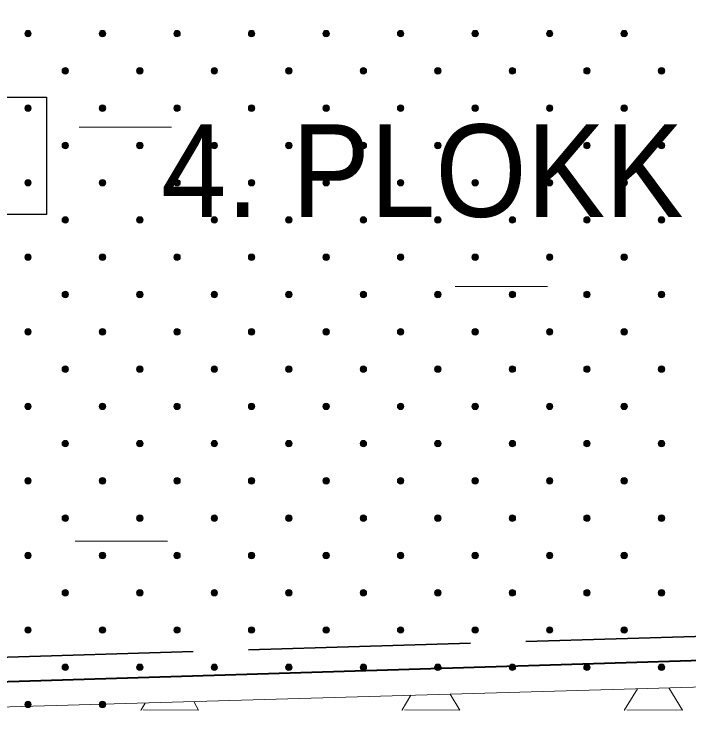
# Model space of a CAD drawing. Extents: x 640104 to 640970, y 6442278 to 6442689.
# Drawn here: x 640905.7 to 640927.6, y 6442508.94 to 6442531.71 of the extents above; entities that cross this region are included whole.
import ezdxf
from ezdxf.enums import TextEntityAlignment as Align

# ---------------------------------------------------------------- set-up
doc = ezdxf.new("R2010")
doc.units = 0
doc.header["$LTSCALE"] = 1.2
doc.linetypes.add('LONG_DASHED', pattern=[7.5, 6, -1.5])
for name, color, linetype, lineweight in [('31', 7, 'Continuous', 13), ('33', 7, 'Continuous', 13), ('35', 7, 'Continuous', 35), ('45', 7, 'Continuous', 13), ('46', 7, 'Continuous', 13), ('47', 7, 'Continuous', 13)]:
    doc.layers.add(name, color=color, linetype=linetype, lineweight=lineweight)

msp = doc.modelspace()

# ---------------------------------------------------------------- hatches: boundary and pattern name
at = {"layer": '45'}
for points in [[(640906.227, 6442531.149, 1), (640906.078, 6442531, 1)], [(640908.645, 6442531.149, 1), (640908.496, 6442531, 1)], [(640911.063, 6442531.149, 1), (640910.915, 6442531, 1)], [(640913.482, 6442531.149, 1), (640913.333, 6442531, 1)], [(640915.9, 6442531.149, 1), (640915.751, 6442531, 1)], [(640918.318, 6442531.149, 1), (640918.17, 6442531, 1)], [(640920.736, 6442531.149, 1), (640920.588, 6442531, 1)], [(640923.155, 6442531.149, 1), (640923.006, 6442531, 1)], [(640925.573, 6442531.149, 1), (640925.425, 6442531, 1)], [(640907.436, 6442529.94, 1), (640907.287, 6442529.791, 1)], [(640909.854, 6442529.94, 1), (640909.706, 6442529.791, 1)], [(640912.272, 6442529.94, 1), (640912.124, 6442529.791, 1)], [(640914.691, 6442529.94, 1), (640914.542, 6442529.791, 1)], [(640917.109, 6442529.94, 1), (640916.961, 6442529.791, 1)], [(640919.527, 6442529.94, 1), (640919.379, 6442529.791, 1)], [(640921.946, 6442529.94, 1), (640921.797, 6442529.791, 1)], [(640924.364, 6442529.94, 1), (640924.215, 6442529.791, 1)], [(640926.782, 6442529.94, 1), (640926.634, 6442529.791, 1)], [(640906.227, 6442528.731, 1), (640906.078, 6442528.582, 1)], [(640908.645, 6442528.731, 1), (640908.496, 6442528.582, 1)], [(640911.063, 6442528.731, 1), (640910.915, 6442528.582, 1)], [(640913.482, 6442528.731, 1), (640913.333, 6442528.582, 1)], [(640915.9, 6442528.731, 1), (640915.751, 6442528.582, 1)], [(640918.318, 6442528.731, 1), (640918.17, 6442528.582, 1)], [(640920.736, 6442528.731, 1), (640920.588, 6442528.582, 1)], [(640923.155, 6442528.731, 1), (640923.006, 6442528.582, 1)], [(640925.573, 6442528.731, 1), (640925.425, 6442528.582, 1)], [(640907.436, 6442527.522, 1), (640907.287, 6442527.373, 1)], [(640909.854, 6442527.522, 1), (640909.706, 6442527.373, 1)], [(640912.272, 6442527.522, 1), (640912.124, 6442527.373, 1)], [(640914.691, 6442527.522, 1), (640914.542, 6442527.373, 1)], [(640917.109, 6442527.522, 1), (640916.961, 6442527.373, 1)], [(640919.527, 6442527.522, 1), (640919.379, 6442527.373, 1)], [(640921.946, 6442527.522, 1), (640921.797, 6442527.373, 1)], [(640924.364, 6442527.522, 1), (640924.215, 6442527.373, 1)], [(640926.782, 6442527.522, 1), (640926.634, 6442527.373, 1)], [(640906.227, 6442526.312, 1), (640906.078, 6442526.164, 1)], [(640908.645, 6442526.312, 1), (640908.496, 6442526.164, 1)], [(640911.063, 6442526.312, 1), (640910.915, 6442526.164, 1)], [(640913.482, 6442526.312, 1), (640913.333, 6442526.164, 1)], [(640915.9, 6442526.312, 1), (640915.751, 6442526.164, 1)], [(640918.318, 6442526.312, 1), (640918.17, 6442526.164, 1)], [(640920.736, 6442526.312, 1), (640920.588, 6442526.164, 1)], [(640923.155, 6442526.312, 1), (640923.006, 6442526.164, 1)], [(640925.573, 6442526.312, 1), (640925.425, 6442526.164, 1)], [(640907.436, 6442525.103, 1), (640907.287, 6442524.955, 1)], [(640909.854, 6442525.103, 1), (640909.706, 6442524.955, 1)], [(640912.272, 6442525.103, 1), (640912.124, 6442524.955, 1)], [(640914.691, 6442525.103, 1), (640914.542, 6442524.955, 1)], [(640917.109, 6442525.103, 1), (640916.961, 6442524.955, 1)], [(640919.527, 6442525.103, 1), (640919.379, 6442524.955, 1)], [(640921.946, 6442525.103, 1), (640921.797, 6442524.955, 1)], [(640924.364, 6442525.103, 1), (640924.215, 6442524.955, 1)], [(640926.782, 6442525.103, 1), (640926.634, 6442524.955, 1)], [(640906.227, 6442523.894, 1), (640906.078, 6442523.746, 1)], [(640908.645, 6442523.894, 1), (640908.496, 6442523.746, 1)], [(640911.063, 6442523.894, 1), (640910.915, 6442523.746, 1)], [(640913.482, 6442523.894, 1), (640913.333, 6442523.746, 1)], [(640915.9, 6442523.894, 1), (640915.751, 6442523.746, 1)], [(640918.318, 6442523.894, 1), (640918.17, 6442523.746, 1)], [(640920.736, 6442523.894, 1), (640920.588, 6442523.746, 1)], [(640923.155, 6442523.894, 1), (640923.006, 6442523.746, 1)], [(640925.573, 6442523.894, 1), (640925.425, 6442523.746, 1)], [(640907.436, 6442522.685, 1), (640907.287, 6442522.536, 1)], [(640909.854, 6442522.685, 1), (640909.706, 6442522.536, 1)], [(640912.272, 6442522.685, 1), (640912.124, 6442522.536, 1)], [(640914.691, 6442522.685, 1), (640914.542, 6442522.536, 1)], [(640917.109, 6442522.685, 1), (640916.961, 6442522.536, 1)], [(640919.527, 6442522.685, 1), (640919.379, 6442522.536, 1)], [(640921.946, 6442522.685, 1), (640921.797, 6442522.536, 1)], [(640924.364, 6442522.685, 1), (640924.215, 6442522.536, 1)], [(640926.782, 6442522.685, 1), (640926.634, 6442522.536, 1)], [(640906.227, 6442521.476, 1), (640906.078, 6442521.327, 1)], [(640908.645, 6442521.476, 1), (640908.496, 6442521.327, 1)], [(640911.063, 6442521.476, 1), (640910.915, 6442521.327, 1)], [(640913.482, 6442521.476, 1), (640913.333, 6442521.327, 1)], [(640915.9, 6442521.476, 1), (640915.751, 6442521.327, 1)], [(640918.318, 6442521.476, 1), (640918.17, 6442521.327, 1)], [(640920.736, 6442521.476, 1), (640920.588, 6442521.327, 1)], [(640923.155, 6442521.476, 1), (640923.006, 6442521.327, 1)], [(640925.573, 6442521.476, 1), (640925.425, 6442521.327, 1)], [(640907.436, 6442520.267, 1), (640907.287, 6442520.118, 1)], [(640909.854, 6442520.267, 1), (640909.706, 6442520.118, 1)], [(640912.272, 6442520.267, 1), (640912.124, 6442520.118, 1)], [(640914.691, 6442520.267, 1), (640914.542, 6442520.118, 1)], [(640917.109, 6442520.267, 1), (640916.961, 6442520.118, 1)], [(640919.527, 6442520.267, 1), (640919.379, 6442520.118, 1)], [(640921.946, 6442520.267, 1), (640921.797, 6442520.118, 1)], [(640924.364, 6442520.267, 1), (640924.215, 6442520.118, 1)], [(640926.782, 6442520.267, 1), (640926.634, 6442520.118, 1)], [(640906.227, 6442519.057, 1), (640906.078, 6442518.909, 1)], [(640908.645, 6442519.057, 1), (640908.496, 6442518.909, 1)], [(640911.063, 6442519.057, 1), (640910.915, 6442518.909, 1)], [(640913.482, 6442519.057, 1), (640913.333, 6442518.909, 1)], [(640915.9, 6442519.057, 1), (640915.751, 6442518.909, 1)], [(640918.318, 6442519.057, 1), (640918.17, 6442518.909, 1)], [(640920.736, 6442519.057, 1), (640920.588, 6442518.909, 1)], [(640923.155, 6442519.057, 1), (640923.006, 6442518.909, 1)], [(640925.573, 6442519.057, 1), (640925.425, 6442518.909, 1)], [(640907.436, 6442517.848, 1), (640907.287, 6442517.7, 1)], [(640909.854, 6442517.848, 1), (640909.706, 6442517.7, 1)], [(640912.272, 6442517.848, 1), (640912.124, 6442517.7, 1)], [(640914.691, 6442517.848, 1), (640914.542, 6442517.7, 1)], [(640917.109, 6442517.848, 1), (640916.961, 6442517.7, 1)], [(640919.527, 6442517.848, 1), (640919.379, 6442517.7, 1)], [(640921.946, 6442517.848, 1), (640921.797, 6442517.7, 1)], [(640924.364, 6442517.848, 1), (640924.215, 6442517.7, 1)], [(640926.782, 6442517.848, 1), (640926.634, 6442517.7, 1)], [(640906.227, 6442516.639, 1), (640906.078, 6442516.491, 1)], [(640908.645, 6442516.639, 1), (640908.496, 6442516.491, 1)], [(640911.063, 6442516.639, 1), (640910.915, 6442516.491, 1)], [(640913.482, 6442516.639, 1), (640913.333, 6442516.491, 1)], [(640915.9, 6442516.639, 1), (640915.751, 6442516.491, 1)], [(640918.318, 6442516.639, 1), (640918.17, 6442516.491, 1)], [(640920.736, 6442516.639, 1), (640920.588, 6442516.491, 1)], [(640923.155, 6442516.639, 1), (640923.006, 6442516.491, 1)], [(640925.573, 6442516.639, 1), (640925.425, 6442516.491, 1)], [(640907.436, 6442515.43, 1), (640907.287, 6442515.282, 1)], [(640909.854, 6442515.43, 1), (640909.706, 6442515.282, 1)], [(640912.272, 6442515.43, 1), (640912.124, 6442515.282, 1)], [(640914.691, 6442515.43, 1), (640914.542, 6442515.282, 1)], [(640917.109, 6442515.43, 1), (640916.961, 6442515.282, 1)], [(640919.527, 6442515.43, 1), (640919.379, 6442515.282, 1)], [(640921.946, 6442515.43, 1), (640921.797, 6442515.282, 1)], [(640924.364, 6442515.43, 1), (640924.215, 6442515.282, 1)], [(640926.782, 6442515.43, 1), (640926.634, 6442515.282, 1)], [(640906.227, 6442514.221, 1), (640906.078, 6442514.072, 1)], [(640908.645, 6442514.221, 1), (640908.496, 6442514.072, 1)], [(640911.063, 6442514.221, 1), (640910.915, 6442514.072, 1)], [(640913.482, 6442514.221, 1), (640913.333, 6442514.072, 1)], [(640915.9, 6442514.221, 1), (640915.751, 6442514.072, 1)], [(640918.318, 6442514.221, 1), (640918.17, 6442514.072, 1)], [(640920.736, 6442514.221, 1), (640920.588, 6442514.072, 1)], [(640923.155, 6442514.221, 1), (640923.006, 6442514.072, 1)], [(640925.573, 6442514.221, 1), (640925.425, 6442514.072, 1)], [(640907.436, 6442513.012, 1), (640907.287, 6442512.863, 1)], [(640909.854, 6442513.012, 1), (640909.706, 6442512.863, 1)], [(640912.272, 6442513.012, 1), (640912.124, 6442512.863, 1)], [(640914.691, 6442513.012, 1), (640914.542, 6442512.863, 1)], [(640917.109, 6442513.012, 1), (640916.961, 6442512.863, 1)], [(640919.527, 6442513.012, 1), (640919.379, 6442512.863, 1)], [(640921.946, 6442513.012, 1), (640921.797, 6442512.863, 1)], [(640924.364, 6442513.012, 1), (640924.215, 6442512.863, 1)], [(640926.782, 6442513.012, 1), (640926.634, 6442512.863, 1)], [(640906.227, 6442511.803, 1), (640906.078, 6442511.654, 1)], [(640908.645, 6442511.803, 1), (640908.496, 6442511.654, 1)], [(640911.063, 6442511.803, 1), (640910.915, 6442511.654, 1)], [(640913.482, 6442511.803, 1), (640913.333, 6442511.654, 1)], [(640915.9, 6442511.803, 1), (640915.751, 6442511.654, 1)], [(640918.318, 6442511.803, 1), (640918.17, 6442511.654, 1)], [(640920.736, 6442511.803, 1), (640920.588, 6442511.654, 1)], [(640923.155, 6442511.803, 1), (640923.006, 6442511.654, 1)], [(640925.573, 6442511.803, 1), (640925.425, 6442511.654, 1)], [(640907.436, 6442510.593, 1), (640907.287, 6442510.445, 1)], [(640909.854, 6442510.593, 1), (640909.706, 6442510.445, 1)], [(640912.272, 6442510.593, 1), (640912.124, 6442510.445, 1)], [(640914.691, 6442510.593, 1), (640914.542, 6442510.445, 1)], [(640917.109, 6442510.593, 1), (640916.961, 6442510.445, 1)], [(640919.527, 6442510.593, 1), (640919.379, 6442510.445, 1)], [(640921.946, 6442510.593, 1), (640921.797, 6442510.445, 1)], [(640924.364, 6442510.593, 1), (640924.215, 6442510.445, 1)], [(640926.782, 6442510.593, 1), (640926.634, 6442510.445, 1)], [(640906.227, 6442509.384, 1), (640906.078, 6442509.236, 1)], [(640908.645, 6442509.384, 1), (640908.496, 6442509.236, 1)]]:
    msp.add_hatch(color=256, dxfattribs=at).paths.add_polyline_path(points)

# ---------------------------------------------------------------- linework, layer by layer
at = {"layer": '31'}
msp.add_lwpolyline([(640553.71, 6442558.56), (640570.07, 6442558.94), (640649.85, 6442563.98), (640763.79, 6442536.22), (640808.67, 6442524.48), (640822.17, 6442520.94), (640837.77, 6442517.67), (640873.2, 6442509.45), (640884.27, 6442508.94), (640895.27, 6442508.94), (640947.47, 6442510.44), (640955.05, 6442510.44)], dxfattribs=at)
at = {"layer": '33', "lineweight": 25}
msp.add_lwpolyline([(640898.04, 6442529.01), (640906.75, 6442529.01), (640906.75, 6442525.21), (640898.04, 6442525.21)], close=True, dxfattribs=at)
at = {"layer": '35', "lineweight": 40}
msp.add_lwpolyline([(640822.97, 6442521.59), (640837.94, 6442518.45), (640873.31, 6442510.24), (640884.29, 6442509.74), (640895.3, 6442509.74), (640946.67, 6442511.32)], dxfattribs=at)
at = {"layer": '35', "linetype": 'LONG_DASHED'}
msp.add_lwpolyline([(640885.07, 6442510.54), (640895.32, 6442510.54), (640945.87, 6442512.06)], dxfattribs=at)
at = {"layer": '45'}
for centre in [(640906.152, 6442531.075), (640908.571, 6442531.075), (640910.989, 6442531.075), (640913.407, 6442531.075), (640915.826, 6442531.075), (640918.244, 6442531.075), (640920.662, 6442531.075), (640923.081, 6442531.075), (640925.499, 6442531.075), (640907.362, 6442529.866), (640909.78, 6442529.866), (640912.198, 6442529.866), (640914.616, 6442529.866), (640917.035, 6442529.866), (640919.453, 6442529.866), (640921.871, 6442529.866), (640924.29, 6442529.866), (640926.708, 6442529.866), (640906.152, 6442528.656), (640908.571, 6442528.656), (640910.989, 6442528.656), (640913.407, 6442528.656), (640915.826, 6442528.656), (640918.244, 6442528.656), (640920.662, 6442528.656), (640923.081, 6442528.656), (640925.499, 6442528.656), (640907.362, 6442527.447), (640909.78, 6442527.447), (640912.198, 6442527.447), (640914.616, 6442527.447), (640917.035, 6442527.447), (640919.453, 6442527.447), (640921.871, 6442527.447), (640924.29, 6442527.447), (640926.708, 6442527.447), (640906.152, 6442526.238), (640908.571, 6442526.238), (640910.989, 6442526.238), (640913.407, 6442526.238), (640915.826, 6442526.238), (640918.244, 6442526.238), (640920.662, 6442526.238), (640923.081, 6442526.238), (640925.499, 6442526.238), (640907.362, 6442525.029), (640909.78, 6442525.029), (640912.198, 6442525.029), (640914.616, 6442525.029), (640917.035, 6442525.029), (640919.453, 6442525.029), (640921.871, 6442525.029), (640924.29, 6442525.029), (640926.708, 6442525.029), (640906.152, 6442523.82), (640908.571, 6442523.82), (640910.989, 6442523.82), (640913.407, 6442523.82), (640915.826, 6442523.82), (640918.244, 6442523.82), (640920.662, 6442523.82), (640923.081, 6442523.82), (640925.499, 6442523.82), (640907.362, 6442522.611), (640909.78, 6442522.611), (640912.198, 6442522.611), (640914.616, 6442522.611), (640917.035, 6442522.611), (640919.453, 6442522.611), (640921.871, 6442522.611), (640924.29, 6442522.611), (640926.708, 6442522.611), (640906.152, 6442521.402), (640908.571, 6442521.402), (640910.989, 6442521.402), (640913.407, 6442521.402), (640915.826, 6442521.402), (640918.244, 6442521.402), (640920.662, 6442521.402), (640923.081, 6442521.402), (640925.499, 6442521.402), (640907.362, 6442520.192), (640909.78, 6442520.192), (640912.198, 6442520.192), (640914.616, 6442520.192), (640917.035, 6442520.192), (640919.453, 6442520.192), (640921.871, 6442520.192), (640924.29, 6442520.192), (640926.708, 6442520.192), (640906.152, 6442518.983), (640908.571, 6442518.983), (640910.989, 6442518.983), (640913.407, 6442518.983), (640915.826, 6442518.983), (640918.244, 6442518.983), (640920.662, 6442518.983), (640923.081, 6442518.983), (640925.499, 6442518.983), (640907.362, 6442517.774), (640909.78, 6442517.774), (640912.198, 6442517.774), (640914.616, 6442517.774), (640917.035, 6442517.774), (640919.453, 6442517.774), (640921.871, 6442517.774), (640924.29, 6442517.774), (640926.708, 6442517.774), (640906.152, 6442516.565), (640908.571, 6442516.565), (640910.989, 6442516.565), (640913.407, 6442516.565), (640915.826, 6442516.565), (640918.244, 6442516.565), (640920.662, 6442516.565), (640923.081, 6442516.565), (640925.499, 6442516.565), (640907.362, 6442515.356), (640909.78, 6442515.356), (640912.198, 6442515.356), (640914.616, 6442515.356), (640917.035, 6442515.356), (640919.453, 6442515.356), (640921.871, 6442515.356), (640924.29, 6442515.356), (640926.708, 6442515.356), (640906.152, 6442514.147), (640908.571, 6442514.147), (640910.989, 6442514.147), (640913.407, 6442514.147), (640915.826, 6442514.147), (640918.244, 6442514.147), (640920.662, 6442514.147), (640923.081, 6442514.147), (640925.499, 6442514.147), (640907.362, 6442512.937), (640909.78, 6442512.937), (640912.198, 6442512.937), (640914.616, 6442512.937), (640917.035, 6442512.937), (640919.453, 6442512.937), (640921.871, 6442512.937), (640924.29, 6442512.937), (640926.708, 6442512.937), (640906.152, 6442511.728), (640908.571, 6442511.728), (640910.989, 6442511.728), (640913.407, 6442511.728), (640915.826, 6442511.728), (640918.244, 6442511.728), (640920.662, 6442511.728), (640923.081, 6442511.728), (640925.499, 6442511.728), (640907.362, 6442510.519), (640909.78, 6442510.519), (640912.198, 6442510.519), (640914.616, 6442510.519), (640917.035, 6442510.519), (640919.453, 6442510.519), (640921.871, 6442510.519), (640924.29, 6442510.519), (640926.708, 6442510.519), (640906.152, 6442509.31), (640908.571, 6442509.31)]:
    msp.add_circle(centre, 0.105, dxfattribs=at)
at = {"layer": '46'}
for points in [[(640925.51, 6442509.12), (640925.51, 6442509.14), (640925.93, 6442509.82)], [(640926.95, 6442509.85), (640927.39, 6442509.13), (640925.59, 6442509.14)], [(640918.29, 6442509.12), (640918.29, 6442509.14), (640918.58, 6442509.61)], [(640919.85, 6442509.65), (640920.17, 6442509.13), (640918.37, 6442509.14)], [(640909.81, 6442509.12), (640909.82, 6442509.14), (640909.95, 6442509.36)], [(640911.53, 6442509.41), (640911.69, 6442509.13), (640909.89, 6442509.14)]]:
    msp.add_lwpolyline(points, dxfattribs=at)
at = {"layer": '47'}
for p, q in [((640907.81, 6442528.04), (640910.81, 6442528.04)), ((640920.01, 6442522.87), (640923.01, 6442522.87)), ((640907.68, 6442514.61), (640910.68, 6442514.61))]:
    msp.add_line(p, q, dxfattribs=at)

# ---------------------------------------------------------------- texts
at = {"layer": '35', "width": 0.95}
msp.add_text('4. PLOKK', height=3, dxfattribs=at).set_placement((640918.945, 6442525.13), align=Align.CENTER)

doc.saveas('drawing.dxf')
